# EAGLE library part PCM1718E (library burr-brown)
SoundPlus(TM) Stereo Audio DAC
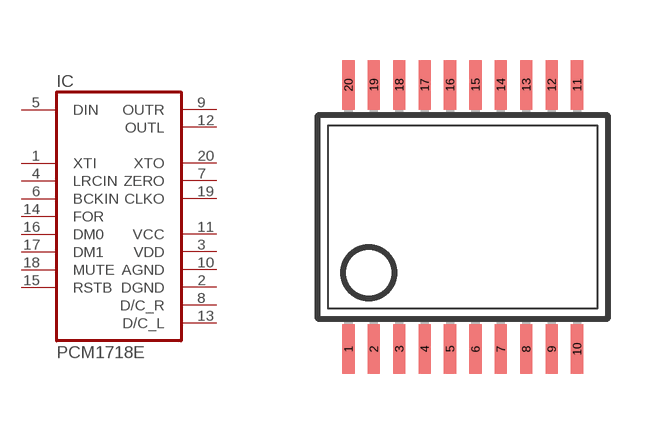
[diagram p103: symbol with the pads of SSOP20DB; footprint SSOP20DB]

Designator prefix IC

## PCM1718E (MF: TEXAS INSTRUMENT CONNECTORS; MPN: PCM1718E; OC_FARNELL: unknown; OC_NEWARK: 35C1942)  [SSOP20DB]
1  XTI  in
2  DGND  pwr
3  VDD  pwr
4  LRCIN  in
5  DIN  in
6  BCKIN  in
7  ZERO  out
8  D/C_R  pwr
9  OUTR  out
10  AGND  pwr
11  VCC  pwr
12  OUTL  out
13  D/C_L  pwr
14  FOR  in
15  RSTB  in
16  DM0  in
17  DM1  in
18  MUTE  in
19  CLKO  out
20  XTO  out

## Footprint SSOP20DB (pad centres in mm)
Small Shrink Outline Package
smd 0.305 x 1.245: 1 -2.857,-3.302; 2 -2.222,-3.302; 3 -1.587,-3.302; 4 -0.952,-3.302; 5 -0.317,-3.302; 6 0.318,-3.302; 7 0.953,-3.302; 8 1.588,-3.302; 9 2.223,-3.302; 10 2.858,-3.302; 11 2.858,3.302; 12 2.223,3.302; 13 1.588,3.302; 14 0.953,3.302; 15 0.318,3.302; 16 -0.317,3.302; 17 -0.952,3.302; 18 -1.587,3.302; 19 -2.222,3.302; 20 -2.857,3.302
